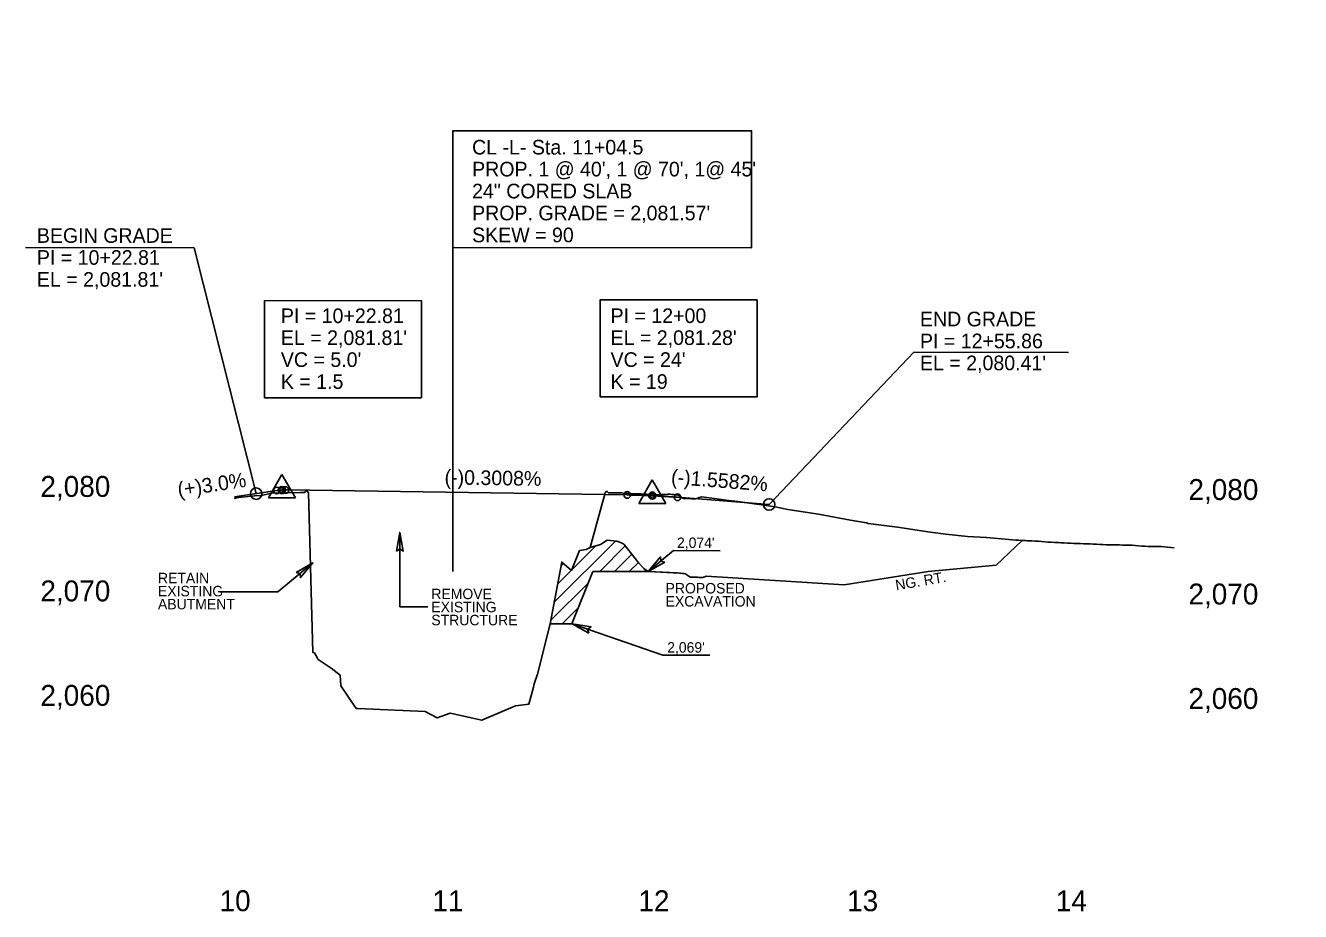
# Model space of a CAD drawing. Extents: x 757145 to 758829, y 592169 to 594973.
# Drawn here: x 757670 to 758280, y 593931 to 594355 of the extents above; entities that cross this region are included whole.
import ezdxf

# ---------------------------------------------------------------- set-up
doc = ezdxf.new("R2010")
doc.units = 0
for name, color, linetype in [('Default', 7, 'Continuous'), ('Exist CMT Alignment Centerline', 7, 'Continuous'), ('Exist CMT EOP', 7, 'Continuous'), ('Old_Level_63', 7, 'Continuous'), ('Prop CMT DNC', 7, 'Continuous'), ('Prop Grid Mask', 7, 'Continuous'), ('Prop Guardrail', 7, 'Continuous'), ('Prop Guardrail Shop Curved', 7, 'Continuous'), ('Prop Roadway Bridge', 7, 'Continuous'), ('Prop Terminator CELL', 7, 'Continuous'), ('Prop Vertical Profile Curve Label', 7, 'Continuous'), ('Prop Vertical Profile Grade Label', 7, 'Continuous')]:
    doc.layers.add(name, color=color, linetype=linetype)

msp = doc.modelspace()

# ---------------------------------------------------------------- linework, layer by layer
at = {"layer": 'Default'}
msp.add_spline([(757891.94, 594602.51), (757928.7, 594613.12), (757974.81, 594621.08), (758013.38, 594621.87), (758059.79, 594614.97), (758103.42, 594606.71), (758144.86, 594596.26), (758186.7, 594584.49), (758228.79, 594570.5), (758271.22, 594556.18), (758311.98, 594537.66), (758352.07, 594519.49), (758392.24, 594498.74), (758431.47, 594479.21), (758471.03, 594457.32), (758502.93, 594438.31), (758541.94, 594414.39), (758575.01, 594392.91), (758612.38, 594365.9), (758644.48, 594342.28), (758681.18, 594311.67), (758729.99, 594270.62), (758760.77, 594240.66)], degree=3, dxfattribs=at)
at = {"layer": 'Exist CMT Alignment Centerline'}
for p, q in [((757769.68, 594129.17), (757789.99, 594132.21)), ((757794.99, 594132.55), (757957.67, 594130.1)), ((757981.68, 594128.99), (758025.54, 594125.57))]:
    msp.add_line(p, q, dxfattribs=at)
for points in [[(757789.99, 594132.21), (757790.09, 594132.23), (757790.19, 594132.24), (757790.29, 594132.26), (757790.39, 594132.27), (757790.49, 594132.28), (757790.59, 594132.3), (757790.69, 594132.31), (757790.79, 594132.32), (757790.89, 594132.33), (757790.99, 594132.35), (757791.09, 594132.36), (757791.19, 594132.37), (757791.29, 594132.38), (757791.39, 594132.39), (757791.49, 594132.4), (757791.59, 594132.41), (757791.69, 594132.42), (757791.79, 594132.43), (757791.89, 594132.44), (757791.99, 594132.45), (757792.09, 594132.46), (757792.19, 594132.46), (757792.29, 594132.47), (757792.39, 594132.48), (757792.49, 594132.49), (757792.59, 594132.49), (757792.69, 594132.5), (757792.79, 594132.5), (757792.89, 594132.51), (757792.99, 594132.51), (757793.09, 594132.52), (757793.19, 594132.52), (757793.29, 594132.53), (757793.39, 594132.53), (757793.49, 594132.54), (757793.59, 594132.54), (757793.69, 594132.54), (757793.79, 594132.54), (757793.89, 594132.55), (757793.99, 594132.55), (757794.09, 594132.55), (757794.19, 594132.55), (757794.29, 594132.55), (757794.39, 594132.55), (757794.49, 594132.55), (757794.59, 594132.55), (757794.69, 594132.55), (757794.79, 594132.55), (757794.89, 594132.55), (757794.99, 594132.55)], [(757957.67, 594130.1), (757958.15, 594130.1), (757958.63, 594130.09), (757959.11, 594130.08), (757959.59, 594130.07), (757960.07, 594130.06), (757960.55, 594130.05), (757961.03, 594130.04), (757961.51, 594130.03), (757961.99, 594130.01), (757962.47, 594130), (757962.95, 594129.99), (757963.43, 594129.97), (757963.91, 594129.96), (757964.39, 594129.94), (757964.87, 594129.93), (757965.35, 594129.91), (757965.83, 594129.89), (757966.31, 594129.88), (757966.79, 594129.86), (757967.28, 594129.84), (757967.76, 594129.82), (757968.24, 594129.8), (757968.72, 594129.78), (757969.2, 594129.76), (757969.68, 594129.74), (757970.16, 594129.71), (757970.64, 594129.69), (757971.12, 594129.67), (757971.6, 594129.64), (757972.08, 594129.62), (757972.56, 594129.59), (757973.04, 594129.56), (757973.52, 594129.54), (757974, 594129.51), (757974.48, 594129.48), (757974.96, 594129.45), (757975.44, 594129.42), (757975.92, 594129.39), (757976.4, 594129.36), (757976.88, 594129.33), (757977.36, 594129.3), (757977.84, 594129.27), (757978.32, 594129.24), (757978.8, 594129.2), (757979.28, 594129.17), (757979.76, 594129.13), (757980.24, 594129.1), (757980.72, 594129.06), (757981.2, 594129.03), (757981.68, 594128.99)]]:
    msp.add_spline(points, degree=3, dxfattribs=at)
at = {"layer": 'Exist CMT EOP'}
for points in [[(757769.66, 594128.44), (757770.22, 594128.61), (757771.76, 594128.94), (757779.37, 594129.67), (757782.45, 594129.93), (757787.54, 594131.01), (757801.29, 594131.27), (757803.34, 594131.33), (757804.2, 594132.33), (757805.16, 594131.2), (757807.3, 594054.72), (757807.96, 594054.64), (757809.73, 594051.38), (757815.97, 594047.17), (757820.23, 594043.84), (757820.65, 594038.74), (757827.98, 594028), (757828.8, 594027.9), (757860.9, 594026.54), (757866.78, 594023.44), (757872.9, 594025.64), (757888, 594022.31), (757904.13, 594029.27), (757910.58, 594030.01), (757912.76, 594038.15), (757913.11, 594039.73), (757914.71, 594044.41), (757920.77, 594068.5), (757926.34, 594097.99), (757930.93, 594093.99), (757934.84, 594103.49), (757937.94, 594103.98), (757939.84, 594104.98), (757945.8, 594126.52), (757946.38, 594128.67), (757947.06, 594131.19), (757947.53, 594131.7), (757948.11, 594131.79), (757948.69, 594131.16), (757949.27, 594131.15), (757949.85, 594131.14), (757950.43, 594131.14), (757951, 594131.13), (757951.58, 594131.12), (757952.16, 594131.11), (757952.74, 594131.1), (757953.32, 594131.1), (757953.89, 594131.09), (757954.47, 594131.08), (757955.05, 594131.07), (757955.63, 594131.02), (757956.79, 594130.82), (757957.36, 594130.79), (757957.94, 594130.76), (757958.52, 594130.73), (757959.1, 594130.72), (757959.68, 594130.7), (757960.26, 594130.69), (757960.83, 594130.67), (757961.41, 594130.66), (757961.99, 594130.64), (757962.57, 594130.62), (757963.15, 594130.61), (757963.72, 594130.59), (757964.3, 594130.57), (757964.88, 594130.55), (757965.46, 594130.53), (757966.04, 594130.49), (757966.62, 594130.45), (757967.19, 594130.4), (757967.77, 594130.36), (757968.35, 594130.32), (757968.93, 594130.27), (757969.51, 594130.24), (757970.09, 594130.23), (757970.66, 594130.22), (757971.24, 594130.21), (757971.82, 594130.21), (757972.4, 594130.22), (757972.98, 594130.24), (757973.55, 594130.26), (757974.15, 594130.28), (757974.71, 594130.31), (757975.29, 594130.33), (757975.87, 594130.36), (757976.45, 594130.39), (757977.02, 594130.42), (757977.6, 594130.44)], [(757977.6, 594130.44), (757978.18, 594130.46), (757978.76, 594130.4), (757979.34, 594130.35), (757979.91, 594130.29), (757980.49, 594130.22), (757981.07, 594130.16), (757981.65, 594130.1), (757982.23, 594129.97), (757982.81, 594129.56), (757983.38, 594129.15), (757983.96, 594128.75), (757984.54, 594128.36), (757985.12, 594128.38), (757985.7, 594128.39), (757986.28, 594128.39), (757987.03, 594128.4), (757987.43, 594128.38), (757988.01, 594128.35), (757988.59, 594128.31), (757989.17, 594128.28), (757989.74, 594128.24), (757990.37, 594128.19), (757990.9, 594128.39), (757991.48, 594128.61), (757992.06, 594128.82), (757992.64, 594129.03), (757993.31, 594129.28), (758001.62, 594128.08), (758006.01, 594127.48), (758010.49, 594126.91), (758018.35, 594125.79), (758022.97, 594125.25), (758028.35, 594124.37), (758034.51, 594123.22), (758049.16, 594120.84), (758064.48, 594117.98), (758072.06, 594116.75), (758072.98, 594116.5), (758086.87, 594114.76), (758102.54, 594112.23), (758110.06, 594111.3), (758120.39, 594110.31), (758129.48, 594109.77), (758140.16, 594108.73), (758141.95, 594108.63), (758143.49, 594108.54), (758145.04, 594108.45), (758146.59, 594108.35), (758148.13, 594108.26), (758148.93, 594108.21), (758149.68, 594108.17), (758151.22, 594108.09), (758152.77, 594108.01), (758154.32, 594107.92), (758155.86, 594107.8), (758157.41, 594107.68), (758158.95, 594107.55), (758159.93, 594107.47), (758160.5, 594107.45), (758162.05, 594107.38), (758163.59, 594107.32), (758163.92, 594107.3), (758165.14, 594107.24), (758166.69, 594107.16), (758168.23, 594107.08), (758169.78, 594107), (758171.32, 594106.96), (758172.87, 594106.91), (758174.42, 594106.86), (758175.96, 594106.8), (758177.51, 594106.73), (758179.05, 594106.66), (758180.6, 594106.59), (758182.15, 594106.52), (758183.69, 594106.45), (758185.24, 594106.38), (758186.79, 594106.31), (758188.33, 594106.28), (758189.88, 594106.25), (758191.42, 594106.22), (758193.14, 594106.18), (758194.52, 594106.16), (758196.06, 594106.14), (758197.61, 594106.12), (758197.93, 594106.12), (758199.15, 594106.02), (758200.7, 594105.9), (758202.25, 594105.77), (758203.79, 594105.65), (758205.34, 594105.53), (758206.89, 594105.52), (758208.43, 594105.5), (758209.98, 594105.48), (758211.52, 594105.46), (758212.22, 594105.46), (758213.07, 594105.38), (758214.62, 594105.25), (758216.16, 594105.12), (758217.71, 594104.99), (758219.26, 594104.85)], [(757980.89, 594092.81), (757981.47, 594092.83), (757967.63, 594093.45), (757982.62, 594092.71), (757983.2, 594092.65), (757983.78, 594092.59), (757984.36, 594092.53), (757984.94, 594092.46), (757985.51, 594092.33), (757986.09, 594091.93), (757986.67, 594091.52), (757987.25, 594091.11), (757987.83, 594090.73), (757988.41, 594090.74), (757988.98, 594090.75), (757989.56, 594090.76), (757990.32, 594090.76), (757990.72, 594090.74), (757991.3, 594090.71), (757991.88, 594090.68), (757992.45, 594090.64), (757993.03, 594090.6), (757993.66, 594090.55), (757994.19, 594090.75), (757994.77, 594090.97), (757995.34, 594091.18), (758061.36, 594087.09), (758101.64, 594093.41), (758134.14, 594096.56), (758146.59, 594108.35)]]:
    msp.add_lwpolyline(points, dxfattribs=at)
at = {"layer": 'Prop Grid Mask'}
for points in [[(757874.27, 594248.49), (758017.13, 594248.45), (758017.15, 594304.4), (757874.28, 594304.44)], [(757784.03, 594176.65), (757859.14, 594176.63), (757859.15, 594223.07), (757784.05, 594223.09)], [(757944.64, 594177.03), (758019.74, 594177.01), (758019.76, 594223.45), (757944.65, 594223.47)]]:
    msp.add_lwpolyline(points, close=True, dxfattribs=at)
at = {"layer": 'Prop Guardrail'}
for p, q in [((757848.83, 594076.54), (757848.78, 594112.21)), ((757922.72, 594078.83), (757951.98, 594108.04)), ((757931.01, 594094.17), (757942.69, 594105.83)), ((757944.47, 594093.48), (757956.73, 594105.72)), ((757807.24, 594097.6), (757790.55, 594083.79)), ((757951.54, 594093.47), (757959.85, 594101.76)), ((757958.61, 594093.46), (757962.96, 594097.81)), ((757967.63, 594093.45), (757979.72, 594103.46)), ((757979.72, 594103.46), (758002.16, 594103.45)), ((757924.36, 594087.54), (757930.88, 594094.04)), ((757931.2, 594068.49), (757941.22, 594093.48)), ((757941.22, 594093.48), (757967.63, 594093.45)), ((757921.08, 594070.13), (757939.05, 594088.07)), ((757762.74, 594083.8), (757790.55, 594083.79)), ((757848.83, 594076.54), (757862.2, 594076.53)), ((757926.52, 594068.49), (757934.33, 594076.29)), ((757920.77, 594068.5), (757931.2, 594068.49)), ((757931.23, 594068.44), (757974.71, 594053.46)), ((757974.71, 594053.46), (757997.14, 594053.45))]:
    msp.add_line(p, q, dxfattribs=at)
msp.add_lwpolyline([(757967.63, 594093.45), (757965.53, 594094.96), (757963.24, 594097.46), (757956.15, 594106.47), (757955.25, 594106.97), (757952.65, 594107.97), (757948.05, 594108.47), (757944.85, 594106.48), (757939.84, 594104.98), (757937.94, 594103.98), (757934.84, 594103.49), (757930.93, 594093.99), (757926.34, 594097.99), (757920.77, 594068.5)], dxfattribs=at)
at = {"layer": 'Prop Guardrail Shop Curved'}
for p, q in [((757792.44, 594139.94), (757785.99, 594128.74)), ((757792.44, 594139.94), (757798.94, 594128.74)), ((757969.63, 594137.27), (757963.17, 594126.08)), ((757969.63, 594137.27), (757976.12, 594126.07)), ((757785.99, 594128.74), (757798.94, 594128.74)), ((757963.17, 594126.08), (757976.12, 594126.07))]:
    msp.add_line(p, q, dxfattribs=at)
for centre, radius in [((757792.44, 594132.46), 1.75), ((757792.44, 594132.46), 1.2), ((757969.63, 594129.79), 1.75), ((757969.63, 594129.79), 1.2)]:
    msp.add_circle(centre, radius, dxfattribs=at)
at = {"layer": 'Prop Roadway Bridge'}
for p, q in [((757874.22, 594093.48), (757874.27, 594248.49)), ((757926.34, 594097.99), (757920.77, 594068.5))]:
    msp.add_line(p, q, dxfattribs=at)
at = {"layer": 'Prop Terminator CELL'}
for p, q in [((757926.01, 594096.24), (757927.1, 594097.33)), ((757965.68, 594093.46), (757966.5, 594094.27))]:
    msp.add_line(p, q, dxfattribs=at)
for points in [[(757847.24, 594103.21), (757848.78, 594112.21), (757850.39, 594103.17), (757848.79, 594104.31)], [(757799.32, 594093.06), (757807.24, 594097.6), (757801.29, 594090.6), (757801.15, 594092.56)], [(757975.55, 594098), (757967.63, 594093.45), (757973.58, 594100.46), (757973.72, 594098.49)], [(757939.23, 594064.04), (757931.23, 594068.44), (757940.31, 594067.01), (757938.7, 594065.87)]]:
    msp.add_lwpolyline(points, close=True, dxfattribs=at)
at = {"layer": 'Prop Vertical Profile Grade Label'}
for p, q in [((757669.77, 594248.55), (757750.38, 594248.41)), ((757750.38, 594248.41), (757780.11, 594130.73)), ((758025.54, 594125.57), (758094.75, 594198.42)), ((758094.75, 594198.42), (758168.72, 594198.29)), ((757789.99, 594132.21), (757792.49, 594132.59)), ((757794.99, 594132.55), (757792.49, 594132.59)), ((757957.67, 594130.1), (757969.68, 594129.92)), ((757981.68, 594128.99), (757969.68, 594129.92))]:
    msp.add_line(p, q, dxfattribs=at)
for centre, radius in [((757794.19, 594132.46), 1.59), ((757780.11, 594130.73), 2.75), ((757789.99, 594132.21), 1.59), ((757957.67, 594130.1), 1.59), ((757981.68, 594128.99), 1.59), ((758025.54, 594125.57), 2.75)]:
    msp.add_circle(centre, radius, dxfattribs=at)

# ---------------------------------------------------------------- texts
at = {"layer": 'Old_Level_63'}
for s, p in [('2,080', (757676.89, 594129.19)), ('2,080', (758226.12, 594127.7)), ('2,070', (757676.89, 594079.19)), ('2,070', (758226.12, 594077.7)), ('2,060', (757676.89, 594029.19)), ('2,060', (758226.12, 594027.7))]:
    msp.add_text(s, height=10, dxfattribs=at).set_placement(p)
at = {"layer": 'Prop CMT DNC'}
for s, p in [('10', (757762.6, 593930.92)), ('11', (757864.44, 593930.92)), ('12', (757962.99, 593930.92)), ('13', (758062.83, 593930.92)), ('14', (758162.67, 593930.92))]:
    msp.add_text(s, height=10, dxfattribs=at).set_placement(p)
at = {"layer": 'Prop Guardrail'}
for s, rotation, p in [("2,074'", 359.9825, (757981.44, 594104.75)), ('RETAIN', 359.9825, (757733.14, 594087.87)), ('NG. RT.', 9.70651, (758086.38, 594084.42)), ('EXISTING', 359.9825, (757733.14, 594081.62)), ('REMOVE', 359.9825, (757863.92, 594080.25)), ('PROPOSED', 359.9825, (757975.99, 594082.98)), ('ABUTMENT', 359.9825, (757733.14, 594075.37)), ('EXCAVATION', 359.9825, (757975.99, 594076.73)), ('EXISTING', 359.9825, (757863.92, 594074)), ('STRUCTURE', 359.9825, (757863.92, 594067.75)), ("2,069'", 359.9825, (757976.76, 594054.67))]:
    msp.add_text(s, height=5, rotation=rotation, dxfattribs=at).set_placement(p)
at = {"layer": 'Prop Vertical Profile Curve Label'}
for s, rotation, p in [('(+)3.0%', 8.53077, (757743.07, 594129.17)), ('(-)0.3008%', 359.13847, (757870.21, 594135.15)), ('(-)1.5582%', 355.54514, (757978.44, 594135.41))]:
    msp.add_text(s, height=7, rotation=rotation, dxfattribs=at).set_placement(p)
at = {"layer": 'Prop Vertical Profile Grade Label'}
for s, p in [('CL -L- Sta. 11+04.5', (757883.42, 594293.04)), ("PROP. 1 @ 40', 1 @ 70', 1@ 45'", (757883.42, 594282.54)), ('24" CORED SLAB', (757883.42, 594272.04)), ("PROP. GRADE = 2,081.57'", (757883.42, 594261.54)), ('BEGIN GRADE', (757675.21, 594250.76)), ('SKEW = 90', (757883.42, 594251.04)), ('PI = 10+22.81', (757675.21, 594240.26)), ("EL = 2,081.81'", (757675.21, 594229.76)), ('PI = 10+22.81', (757791.94, 594212.37)), ('PI = 12+00', (757949.66, 594212.39)), ('END GRADE', (758097.68, 594210.8)), ("EL = 2,081.81'", (757791.94, 594201.87)), ("EL = 2,081.28'", (757949.66, 594201.89)), ('PI = 12+55.86', (758097.68, 594200.3)), ("VC = 5.0'", (757791.94, 594191.37)), ("VC = 24'", (757949.66, 594191.39)), ("EL = 2,080.41'", (758097.68, 594189.8)), ('K = 1.5', (757791.94, 594180.87)), ('K = 19', (757949.66, 594180.89))]:
    msp.add_text(s, height=7, dxfattribs=at).set_placement(p)

doc.saveas('drawing.dxf')
